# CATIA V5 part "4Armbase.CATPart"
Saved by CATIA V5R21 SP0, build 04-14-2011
Part number: Armbase
Bounding box of the stored display mesh (mm): x -36 to 36, y -57.294 to 35, z 0 to 84.554
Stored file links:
  F:\教程\Robotic_Arm_Arduino_Kinect\机械臂CAD\Arm_Detailed_Design_Assembly\Armbase.CATPart
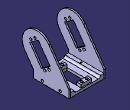
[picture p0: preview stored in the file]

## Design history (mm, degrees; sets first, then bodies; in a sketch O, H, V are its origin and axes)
Body1 (main body)
  Sketch1 on zx-plane, origin (0, 0, 0), H (-1, 0, 0), V (0, 0, 1)
    point P1 (-33, 0)
    line L1 (-33, 0) -> (-33, 9)
    point P2 (-33, 9)
    line L2 (-33, 9) -> (-26, 9)
    point P3 (-26, 9)
    line L3 (-26, 9) -> (-26, 5)
    point P4 (-26, 5)
    line L4 (-26, 5) -> (0, 5)
    point P5 (0, 5)
    line L5 (-33, 0) -> (0, 0)
    point P6 (0, 5)
    point P7 (26, 5)
    line L6 (26, 5) -> (0, 5)
    point P8 (26, 9)
    line L7 (26, 9) -> (26, 5)
    point P9 (33, 9)
    line L8 (33, 9) -> (26, 9)
    point P10 (33, 0)
    line L9 (33, 0) -> (33, 9)
    point P11 (0, 0)
    line L10 (33, 0) -> (0, 0)
    length L5 = 33
    distance L4 L5 = 5
    distance L2 L4 = 4
    length L2 = 7
    coincidence: P1 H, P5 V, O P11, P5 P6
    vertical: L1 V, L3 V
    horizontal: L2 H, L4 H, L5 H
    symmetry: P5 P6 V, P4 P7 V, L4 L6 V, P3 P8 V, L3 L7 V, P2 P9 V, L2 L8 V, P1 P10 V, L1 L9 V, O P11 V, L5 L10 V
  Pad1: profile Sketch1, direction (0, 1, 0), length 35, mirrored extent
  Fillet1: radius 4, on edge [face of Pad1 from Sketch1.L3 | face of Pad1 from Sketch1.L4]; edge [face of Pad1 from Sketch1.L6 | face of Pad1 from Sketch1.L7]
  Sketch2 on face of Pad1 from Sketch1.L6, origin (0, 0, 5), H (1, 0, 0), V (0, 1, 0)
    line L1 (-10.5, 25) -> (10.5, 25)
    line L2 (10.5, 25) -> (10.5, -15.5)
    line L3 (10.5, -15.5) -> (-10.5, -15.5)
    line L4 (-10.5, -15.5) -> (-10.5, 25)
    circle A1 centre (-5, 29) radius 2.5
    point P5 (-5, 29)
    circle A2 centre (5, 29) radius 2.5
    point P6 (5, 29)
    circle A3 centre (-5, -19.5) radius 2.5
    point P7 (-5, -19.5)
    circle A4 centre (5, -19.5) radius 2.5
    point P8 (5, -19.5)
    construction circle A5 centre (0, 15.34) radius 2.8695
    point P9 (0, 15.34)
    axis line L5 (-19.0638, 15.34) -> (25.8227, 15.34)
    length L2 = 40.5
    length L1 = 21
    distance L1 H = 25
    distance L2 V = 10.5
    radius A1 = 2.5
    radius A2 = 2.5
    radius A4 = 2.5
    distance P9 L1 = 9.66
    distance P6 L5 = 13.66
    distance P5 L5 = 13.66
    distance P5 P6 = 10
    distance P7 L5 = 34.84
    distance L5 P8 = 34.84
    distance P8 P7 = 10
    radius A3 = 2.5
    distance P5 V = 5
    distance V P7 = 5
    horizontal: L1 H, L3 H, L5 H
    vertical: L2 V, L4 V
    coincidence: P9 V, L5 P9
  Pocket1: profile Sketch2, direction (0, 0, -1), length 5
  Fillet2: radius 0.5, on edge [face of Pocket1 from Sketch2.L2 | face of Pocket1 from Sketch2.L3]; edge [face of Pocket1 from Sketch2.L1 | face of Pocket1 from Sketch2.L2]; edge [face of Pocket1 from Sketch2.L4 | face of Pocket1 from Sketch2.L1]; edge [face of Pocket1 from Sketch2.L3 | face of Pocket1 from Sketch2.L4]
  Sketch3 on face of Pad1 from Sketch1.L9, origin (-33, 0, 0), H (0, -1, 0), V (0, 0, 1)
    circle A1 centre (-17.5, 4.5) radius 2.5
    point P1 (-17.5, 4.5)
    reference projected line E1 (35, 0) -> (-35, 0) from edge [face of Pad1 from Sketch1.L9 | face of Pad1 from Sketch1.L10]
    circle A2 centre (17.5, 4.5) radius 2.5
    radius A1 = 2.5
    distance P1 E1 = 4.5
    distance V P1 = 17.5
    symmetry: A1 A2 V
  Pocket2: profile Sketch3, direction (1, 0, 0), length 4
  Sketch4 on face of Pad1 from Sketch1.L1, origin (33, 0, 0), H (0, 1, 0), V (0, 0, 1)
    circle A1 centre (-17.5, 4.5) radius 2.5
    point P1 (-17.5, 4.5)
    reference projected line E1 (-35, 0) -> (35, 0) from edge [face of Pad1 from Sketch1.L5 | face of Pad1 from Sketch1.L1]
    circle A2 centre (17.5, 4.5) radius 2.5
    radius A1 = 2.5
    distance P1 V = 17.5
    distance P1 E1 = 4.5
    symmetry: A1 A2 V
  Pocket3: profile Sketch4, direction (-1, 0, 0), length 4
  Sketch5 on face of Pad1, origin (0, 0, 5), H (1, 0, 0), V (0, 1, 0)
    construction circle A1 centre (0, -5.84) radius 32
    point P1 (0, -5.84)
    reference projected line E1 (-26, -35) -> (26, -35) from edge [start face of Pad1 | face of Pad1]
    circle A2 centre (-29, -5.84) radius 1.5
    point P2 (-29, -5.84)
    circle A3 centre (29, -5.84) radius 1.5
    point P3 (29, -5.84)
    distance P1 E1 = 29.16
    radius A1 = 32
    radius A2 = 1.5
    distance P2 P1 = 29
    radius A3 = 1.5
    distance P1 P3 = 29
    coincidence: P1 V
  Pocket4: profile Sketch5, direction (0, 0, -1), length 6, mirrored extent
Body2
  Sketch6 on face of Pad1 from Sketch1.L9, origin (-33, 0, 0), H (0, -1, 0), V (0, 0, 1)
    point P1 (-35, 0)
    line L1 (-35, 0) -> (-35, 15)
    line L2 (-35, 15) -> (5.1504, 72.3406)
    arc A1 centre (28.6357, 55.896) radius 28.6703 from (5.1504, 72.3406) to (52.1211, 39.4514) cw
    line L3 (52.1211, 39.4514) -> (35, 15)
    line L4 (35, 15) -> (35, 0)
    point P7 (35, 0)
    line L5 (35, 0) -> (-35, 0)
    reference projected line E1 (35, 0) -> (35, 9) from edge [start face of Pad1 | face of Pad1 from Sketch1.L9]
    reference projected line E2 (-35, 0) -> (-35, 9) from edge [face of Pad1 from Sketch1.L9 | end face of Pad1]
    circle A2 centre (-17.5, 4.5) radius 2
    point P8 (-17.5, 4.5)
    circle A3 centre (17.5, 4.5) radius 2
    angle L2 L1 = 145
    length L1 = 15
    length L4 = 15
    length L2 = 70
    radius A2 = 2
    distance P8 L5 = 4.5
    distance P8 V = 17.5
    coincidence: P1 H, P7 H, L4 E1, L1 E2
    vertical: L1 V, L4 V
    tangency: A1 L2, L3 A1
    horizontal: L5 H
    parallelism: L3 L2
    symmetry: A2 A3 V
  Pad2: profile Sketch6, direction (-1, 0, 0), length 3
  Sketch7 on end face of Pad2, origin (-36, 0, 0), H (0, -1, 0), V (0, 0, 1)
    line L1 (25.5754, 69.8316) -> (42.7775, 57.7865)
    line L2 (42.7775, 57.7865) -> (19.5477, 24.6108)
    line L3 (19.5477, 24.6108) -> (2.3455, 36.6559)
    line L4 (2.3455, 36.6559) -> (25.5754, 69.8316)
    reference projected line E1 (1.258, 66.7818) -> (-33.1566, 17.6327) from edge [face of Pad2 from Sketch6.L2 | end face of Pad2]
    construction circle A1 centre (28.6357, 55.896) radius 3.7662
    point P5 (28.6357, 55.896)
    reference projected arc E2 centre (28.6357, 55.896) radius 28.6703 from (50.5984, 37.4671) to (6.673, 74.3249) ccw from edge [face of Pad2 from Sketch6.A1 | end face of Pad2]
    circle A2 centre (32.375, 69.9535) radius 2.5
    point P6 (32.375, 69.9535)
    circle A3 centre (40.5665, 64.2178) radius 2.5
    point P7 (40.5665, 64.2178)
    axis line L5 (44.6915, 44.6536) -> (17.7883, 63.4915)
    circle A4 centre (4.5565, 30.2246) radius 2.5
    point P10 (4.5565, 30.2246)
    circle A5 centre (12.7481, 24.4889) radius 2.5
    point P11 (12.7481, 24.4889)
    length L1 = 21
    length L2 = 40.5
    distance P5 L2 = 10.5
    distance P5 L1 = 9.66
    radius A2 = 2.5
    radius A3 = 2.5
    distance P6 L5 = 13.66
    distance P7 L5 = 13.66
    distance P6 P7 = 10
    distance P6 L4 = 5.5
    radius A4 = 2.5
    radius A5 = 2.5
    distance P10 P11 = 10
    length L5 = 32.8428
    distance P11 L5 = 34.84
    distance P10 L4 = 5.5
    distance L5 P10 = 34.84
    parallelism: L4 L2, L1 L3, L4 E1, L5 L1
    perpendicularity: L1 L2
    concentricity: A1 E2
    coincidence: L5 P5
  Pocket5: profile Sketch7, direction (1, 0, 0), length 5
  Fillet3: radius 0.5, on edge [face of Pocket5 from Sketch7.L3 | face of Pocket5 from Sketch7.L4]; edge [face of Pocket5 from Sketch7.L2 | face of Pocket5 from Sketch7.L3]; edge [face of Pocket5 from Sketch7.L1 | face of Pocket5 from Sketch7.L2]; edge [face of Pocket5 from Sketch7.L4 | face of Pocket5 from Sketch7.L1]
  Sketch8 on face of Pad1 from Sketch1.L1, origin (33, 0, 0), H (0, 1, 0), V (0, 0, 1)
    projected line E1 (35, 0) -> (-35, 0) from edge [start face of Pad2 | face of Pad2 from Sketch6.L5]
    projected line E2 (-35, 0) -> (-35, 15) from edge [start face of Pad2 | face of Pad2 from Sketch6.L4]
    projected line E3 (-35, 15) -> (-52.1211, 39.4514) from edge [start face of Pad2 | face of Pad2 from Sketch6.L3]
    projected arc E4 centre (-28.6357, 55.896) radius 28.6703 from (-5.1504, 72.3406) to (-52.1211, 39.4514) ccw from edge [start face of Pad2 | face of Pad2 from Sketch6.A1]
    projected line E5 (-5.1504, 72.3406) -> (35, 15) from edge [start face of Pad2 | face of Pad2 from Sketch6.L2]
    projected line E6 (35, 15) -> (35, 0) from edge [start face of Pad2 | face of Pad2 from Sketch6.L1]
    projected arc E7 centre (-25.6981, 69.1352) radius 0.5 from (-25.2886, 69.422) to (-25.9849, 69.5448) ccw from edge [face of Fillet3 | start face of Pad2]
    projected line E8 (-25.9849, 69.5448) -> (-42.368, 58.0733) from edge [start face of Pad2 | face of Pocket5 from Sketch7.L1]
    projected arc E9 centre (-42.0812, 57.6637) radius 0.5 from (-42.368, 58.0733) to (-42.4908, 57.3769) ccw from edge [face of Fillet3 | start face of Pad2]
    projected line E10 (-42.4908, 57.3769) -> (-19.8345, 25.0204) from edge [start face of Pad2 | face of Pocket5 from Sketch7.L2]
    projected arc E11 centre (-19.4249, 25.3072) radius 0.5 from (-19.8345, 25.0204) to (-19.1381, 24.8976) ccw from edge [face of Fillet3 | start face of Pad2]
    projected line E12 (-19.1381, 24.8976) -> (-2.7551, 36.3691) from edge [start face of Pad2 | face of Pocket5 from Sketch7.L3]
    projected arc E13 centre (-3.0419, 36.7787) radius 0.5 from (-2.7551, 36.3691) to (-2.6323, 37.0655) ccw from edge [face of Fillet3 | start face of Pad2]
    projected line E14 (-2.6323, 37.0655) -> (-25.2886, 69.422) from edge [start face of Pad2 | face of Pocket5 from Sketch7.L4]
    projected circle E15 centre (-32.375, 69.9535) radius 2.5 from edge [face of Pocket5 from Sketch7.A2 | start face of Pad2]
    projected circle E16 centre (-40.5665, 64.2178) radius 2.5 from edge [face of Pocket5 from Sketch7.A3 | start face of Pad2]
    projected circle E17 centre (-4.5565, 30.2246) radius 2.5 from edge [face of Pocket5 from Sketch7.A4 | start face of Pad2]
    projected circle E18 centre (-12.7481, 24.4889) radius 2.5 from edge [face of Pocket5 from Sketch7.A5 | start face of Pad2]
    circle A1 centre (-17.5, 4.5) radius 2.5
    point P29 (-17.5, 4.5)
    circle A2 centre (17.5, 4.5) radius 2.5
    radius A1 = 2.5
    distance P29 E1 = 4.5
    distance P29 V = 17.5
    symmetry: A1 A2 V
  Pad3: profile Sketch8, direction (1, 0, 0), length 3
Body3
  Sketch9 on face of Pad1, origin (0, 0, 5), H (1, 0, 0), V (0, 1, 0)
    point P1 (-10.5, 33)
    line L1 (-10.5, 33) -> (10.5, 33)
    line L2 (10.5, 33) -> (10.5, 25)
    line L3 (10.5, 25) -> (-10.5, 25)
    line L4 (-10.5, 25) -> (-10.5, 33)
    point P2 (10.5, 33)
    point P3 (10.5, 25)
    point P4 (-10.5, 25)
    circle A1 centre (5, 29) radius 2.5
    circle A2 centre (-5, 29) radius 2.5
    reference projected circle E1 centre (5, 29) radius 2.5 from edge [face of Pad1 from Sketch1.L4 | face of Pocket1 from Sketch2.A2]
    reference projected circle E2 centre (-5, 29) radius 2.5 from edge [face of Pad1 from Sketch1.L6 | face of Pocket1 from Sketch2.A1]
    reference projected line E3 (10.5, 25) -> (-10.5, 25) from edge [face of Pad1 | face of Pocket1 from Sketch2.L1]
    axis line L5 (51.9835, 4.75) -> (-25.6214, 4.75)
    point P9 (-10.5, -23.5)
    point P10 (10.5, -23.5)
    point P11 (10.5, -15.5)
    point P12 (-10.5, -15.5)
    line L6 (-10.5, -23.5) -> (10.5, -23.5)
    line L7 (10.5, -23.5) -> (10.5, -15.5)
    line L8 (10.5, -15.5) -> (-10.5, -15.5)
    line L9 (-10.5, -15.5) -> (-10.5, -23.5)
    circle A3 centre (5, -19.5) radius 2.5
    circle A4 centre (-5, -19.5) radius 2.5
    length L2 = 8
    length L1 = 21
    distance V L2 = 10.5
    distance L5 L3 = 20.25
    horizontal: L1 H, L3 H, L5 H
    vertical: L2 V, L4 V
    coincidence: A1 E1, A2 E2, L3 E3
    symmetry: P1 P9 L5, P2 P10 L5, P3 P11 L5, P4 P12 L5, L1 L6 L5, L2 L7 L5, L3 L8 L5, L4 L9 L5, A1 A3 L5, A2 A4 L5
  Pad4: profile Sketch9, direction (0, 0, 1), length 6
